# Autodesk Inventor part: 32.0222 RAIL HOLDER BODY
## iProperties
Created: 2011-07
Part Number: 32.0222 RAIL HOLDER BODY
Document SubType Name: Modeling
Designer: Administrator
Density: 7.85 g/cm^3
Material: Steel
Mass: 250.457 g
Surface Area: 207.412 cm^2
Volume: 31.9054 cm^3
Author: Administrator
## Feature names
1. Base1
2. Hole1
